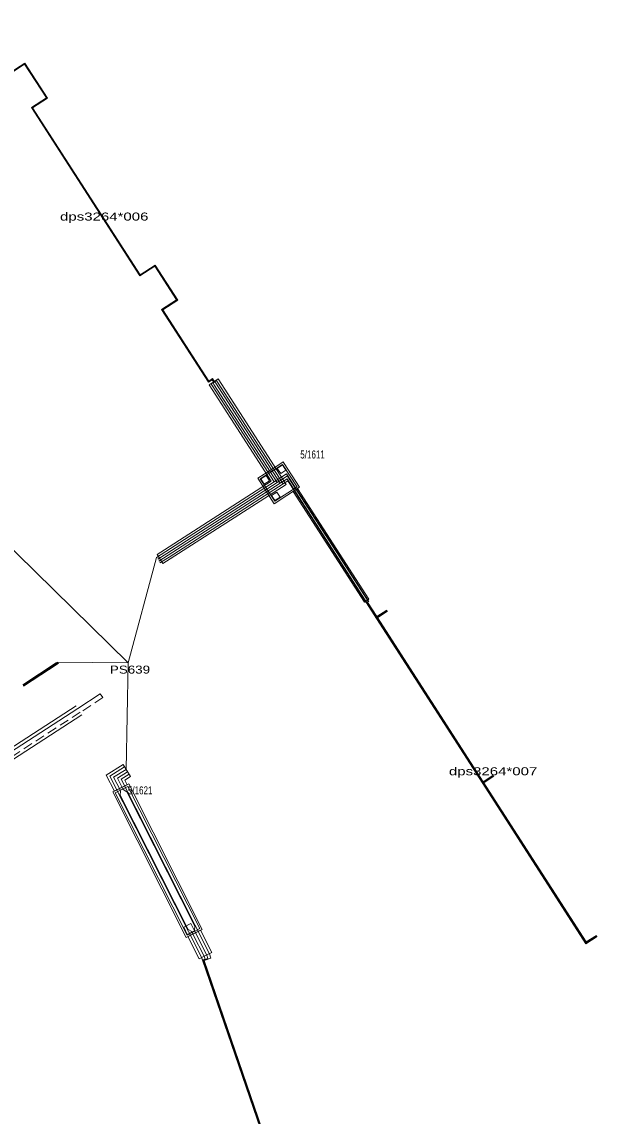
# Model space of a CAD drawing. Extents: x -473467 to -473049, y -1106745 to -1106181.
# Drawn here: x -473135.6 to -473071, y -1106543.7 to -1106420.7 of the extents above; entities that cross this region are included whole.
import ezdxf
from ezdxf.enums import TextEntityAlignment as Align

# ---------------------------------------------------------------- set-up
doc = ezdxf.new("R2010")
doc.units = 0
doc.header["$LTSCALE"] = 0.36
doc.linetypes.add('MEDIUM_DASHED', pattern=[4.5, 3, -1.5])
for name, color, linetype, lineweight in [('1', 7, 'MEDIUM_DASHED', 13), ('11', 7, 'Continuous', 13), ('14', 7, 'Continuous', 13), ('15', 7, 'Continuous', 13), ('17', 7, 'Continuous', 13), ('7', 7, 'Continuous', 13)]:
    doc.layers.add(name, color=color, linetype=linetype, lineweight=lineweight)
for name, color, linetype in [('16', 7, 'Continuous'), ('19', 7, 'Continuous'), ('9', 7, 'Continuous')]:
    doc.layers.add(name, color=color, linetype=linetype)

msp = doc.modelspace()

# ---------------------------------------------------------------- linework, layer by layer
at = {"layer": '1', "linetype": 'Continuous'}
msp.add_lwpolyline([(-473238.151, -1106496.572), (-473233.916, -1106494.611), (-473233.253, -1106494.854), (-473219.66, -1106524.241), (-473218.952, -1106524.731), (-473210.178, -1106525.371), (-473209.213, -1106525.228), (-473205.294, -1106523.722), (-473204.636, -1106524.005), (-473200.526, -1106535.348), (-473199.857, -1106535.779), (-473186.652, -1106534.741), (-473185.734, -1106534.43), (-473129.308, -1106497.84), (-473126.788, -1106496.206)], dxfattribs=at)
at = {"layer": '1'}
msp.add_lwpolyline([(-473126.788, -1106496.206), (-473126.498, -1106496.613), (-473129.036, -1106498.26), (-473185.568, -1106534.919), (-473186.486, -1106535.23), (-473200.197, -1106536.307), (-473200.867, -1106535.877), (-473204.951, -1106524.662), (-473205.589, -1106524.371), (-473209.138, -1106525.735), (-473210.103, -1106525.878), (-473219.282, -1106525.209), (-473219.991, -1106524.719), (-473233.497, -1106495.518), (-473234.16, -1106495.275), (-473237.921, -1106497.017)], dxfattribs=at)
at = {"layer": '11'}
for p, q in [((-473141.383, -1106475.297), (-473123.66, -1106492.696)), ((-473120.467, -1106480.867), (-473123.66, -1106492.696)), ((-473131.524, -1106492.704), (-473135.428, -1106495.272)), ((-473131.579, -1106492.62), (-473123.66, -1106492.696)), ((-473123.886, -1106504.681), (-473123.66, -1106492.696))]:
    msp.add_line(p, q, dxfattribs=at)
for points in [[(-473140.469, -1106420.814), (-473140.587, -1106420.89), (-473136.964, -1106426.509), (-473135.283, -1106425.426), (-473132.845, -1106429.208), (-473134.526, -1106430.291), (-473122.335, -1106449.202), (-473120.654, -1106448.119), (-473118.216, -1106451.901), (-473119.897, -1106452.985), (-473114.632, -1106461.152), (-473114.211, -1106460.881), (-473114.034, -1106461.157)], [(-473140.251, -1106420.71), (-473140.545, -1106420.899), (-473136.955, -1106426.468), (-473135.274, -1106425.384), (-473132.804, -1106429.217), (-473134.485, -1106430.3), (-473122.326, -1106449.161), (-473120.645, -1106448.077), (-473118.174, -1106451.91), (-473119.855, -1106452.994), (-473114.623, -1106461.11), (-473114.202, -1106460.839), (-473114.033, -1106461.102), (-473113.989, -1106461.171)], [(-473140.001, -1106420.655), (-473140.471, -1106420.959), (-473140.413, -1106421.049), (-473136.947, -1106426.426), (-473135.266, -1106425.343), (-473132.762, -1106429.226), (-473134.443, -1106430.309), (-473122.317, -1106449.119), (-473120.636, -1106448.036), (-473118.133, -1106451.919), (-473119.814, -1106453.003), (-473114.614, -1106461.069), (-473114.193, -1106460.798), (-473114.008, -1106461.086), (-473113.963, -1106461.155)], [(-473139.669, -1106420.727), (-473140.14, -1106421.03), (-473140.316, -1106421.144), (-473136.938, -1106426.385), (-473135.257, -1106425.301), (-473132.721, -1106429.235), (-473134.402, -1106430.318), (-473122.308, -1106449.078), (-473120.627, -1106447.994), (-473118.091, -1106451.928), (-473119.772, -1106453.011), (-473114.605, -1106461.027), (-473114.185, -1106460.756), (-473113.957, -1106461.109)], [(-473114.034, -1106461.157), (-473114.335, -1106461.353), (-473114.219, -1106461.534), (-473107.241, -1106472.358)], [(-473113.989, -1106461.171), (-473114.115, -1106461.252), (-473114.017, -1106461.404), (-473106.909, -1106472.43)], [(-473113.963, -1106461.155), (-473113.913, -1106461.123), (-473113.815, -1106461.274), (-473106.577, -1106472.502)], [(-473113.957, -1106461.109), (-473113.73, -1106460.964), (-473113.613, -1106461.144), (-473106.245, -1106472.574)], [(-473107.241, -1106472.358), (-473105.854, -1106471.466), (-473100.257, -1106480.166)], [(-473107.241, -1106472.358), (-473119.436, -1106480.203), (-473120.467, -1106480.867)], [(-473106.909, -1106472.43), (-473119.306, -1106480.405), (-473120.337, -1106481.069)], [(-473106.577, -1106472.502), (-473119.176, -1106480.607), (-473120.208, -1106481.271)], [(-473106.245, -1106472.574), (-473119.046, -1106480.809), (-473120.078, -1106481.473)], [(-473100.296, -1106480.197), (-473105.755, -1106471.712), (-473105.766, -1106471.695), (-473106.909, -1106472.43)], [(-473106.577, -1106472.502), (-473105.804, -1106472.005), (-473100.47, -1106480.297)], [(-473106.245, -1106472.574), (-473105.716, -1106472.234), (-473105.408, -1106472.713), (-473100.512, -1106480.323)], [(-473100.257, -1106480.166), (-473096.732, -1106485.645), (-473096.72, -1106485.664)], [(-473100.512, -1106480.323), (-473096.984, -1106485.808), (-473096.97, -1106485.83)], [(-473100.47, -1106480.297), (-473096.942, -1106485.781), (-473096.928, -1106485.803)], [(-473096.765, -1106485.687), (-473096.774, -1106485.672), (-473100.296, -1106480.197)], [(-473096.97, -1106485.83), (-473096.876, -1106485.976), (-473095.763, -1106487.705), (-473094.502, -1106486.894), (-473095.763, -1106487.705), (-473083.82, -1106506.271), (-473082.558, -1106505.46), (-473083.82, -1106506.271), (-473072.23, -1106524.287), (-473070.968, -1106523.476)], [(-473096.928, -1106485.803), (-473096.834, -1106485.949), (-473096.834, -1106485.949), (-473095.748, -1106487.636), (-473094.539, -1106486.858), (-473095.748, -1106487.636), (-473083.805, -1106506.202), (-473082.594, -1106505.425), (-473083.805, -1106506.202), (-473072.215, -1106524.218), (-473070.995, -1106523.434)], [(-473071.023, -1106523.392), (-473072.2, -1106524.149), (-473083.79, -1106506.133), (-473082.63, -1106505.387), (-473083.79, -1106506.133), (-473095.733, -1106487.567), (-473094.558, -1106486.808), (-473095.733, -1106487.567), (-473096.792, -1106485.922), (-473096.819, -1106485.88), (-473096.693, -1106485.798), (-473096.765, -1106485.687)], [(-473096.72, -1106485.664), (-473096.624, -1106485.813), (-473096.75, -1106485.895), (-473095.718, -1106487.498), (-473094.593, -1106486.77), (-473095.718, -1106487.498), (-473083.775, -1106506.064), (-473082.653, -1106505.343), (-473083.775, -1106506.064), (-473072.185, -1106524.08), (-473071.05, -1106523.35)], [(-473135.483, -1106495.189), (-473131.724, -1106492.716), (-473131.579, -1106492.62)], [(-473135.456, -1106495.231), (-473131.696, -1106492.757), (-473131.551, -1106492.662)], [(-473135.401, -1106495.314), (-473131.641, -1106492.841), (-473131.496, -1106492.745)], [(-473124.056, -1106504.409), (-473124.056, -1106504.409), (-473125.7, -1106505.436), (-473115.407, -1106525.803), (-473115.3, -1106526.116)], [(-473123.886, -1106504.681), (-473123.886, -1106504.681), (-473125.283, -1106505.552), (-473124.554, -1106506.994), (-473124.543, -1106507.016), (-473124.514, -1106507.074), (-473124.556, -1106507.59), (-473116.927, -1106522.686), (-473116.507, -1106522.918), (-473116.332, -1106523.265), (-473115.112, -1106525.678), (-473115.002, -1106525.997)], [(-473123.717, -1106504.952), (-473123.717, -1106504.952), (-473124.865, -1106505.669), (-473124.409, -1106506.572), (-473124.228, -1106506.93), (-473123.788, -1106507.202), (-473116.159, -1106522.298), (-473116.218, -1106522.779), (-473116.051, -1106523.111), (-473114.816, -1106525.553), (-473114.684, -1106525.941)], [(-473123.548, -1106505.224), (-473123.548, -1106505.224), (-473124.448, -1106505.786), (-473114.521, -1106525.429), (-473114.365, -1106525.884)], [(-473115.3, -1106526.116), (-473097.408, -1106578.227), (-473097.077, -1106579.184), (-473096.718, -1106579.06), (-473096.399, -1106578.95)], [(-473115.002, -1106525.997), (-473115.258, -1106526.085), (-473097.413, -1106578.06), (-473097.361, -1106578.211), (-473097.046, -1106579.121), (-473096.74, -1106579.015), (-473096.455, -1106578.916)], [(-473114.684, -1106525.941), (-473115.194, -1106526.116), (-473097.366, -1106578.043), (-473097.314, -1106578.195), (-473097.015, -1106579.057), (-473096.761, -1106578.969), (-473096.525, -1106578.888)], [(-473114.365, -1106525.884), (-473115.131, -1106526.147), (-473097.318, -1106578.027), (-473097.266, -1106578.178), (-473096.985, -1106578.993), (-473096.766, -1106578.918), (-473096.579, -1106578.853)]]:
    msp.add_lwpolyline(points, dxfattribs=at)
at = {"layer": '14'}
for points in [[(-473108.816, -1106472.018), (-473106.295, -1106470.393), (-473104.669, -1106472.914), (-473107.191, -1106474.54), (-473108.816, -1106472.018)], [(-473125.112, -1106507.31), (-473123.684, -1106506.589), (-473115.603, -1106522.577), (-473117.031, -1106523.299), (-473125.112, -1106507.31)]]:
    msp.add_lwpolyline(points, close=True, dxfattribs=at)
at = {"layer": '15'}
for points in [[(-473106.31, -1106470.462), (-473106.898, -1106470.841), (-473106.519, -1106471.429), (-473105.931, -1106471.05)], [(-473108.747, -1106472.033), (-473108.159, -1106471.654), (-473107.78, -1106472.242), (-473108.368, -1106472.621)], [(-473107.176, -1106474.47), (-473106.588, -1106474.091), (-473106.967, -1106473.503), (-473107.555, -1106473.882)], [(-473117.415, -1106522.428), (-473116.612, -1106522.023), (-473116.206, -1106522.826), (-473117.009, -1106523.232), (-473117.415, -1106522.428)]]:
    msp.add_lwpolyline(points, close=True, dxfattribs=at)
at = {"layer": '17'}
for points in [[(-473119.566, -1106480.002), (-473107.573, -1106472.286), (-473114.562, -1106461.445), (-473113.554, -1106460.795), (-473105.913, -1106472.646), (-473118.916, -1106481.011), (-473119.757, -1106481.552), (-473120.407, -1106480.543)], [(-473106.235, -1106470.116), (-473106.403, -1106470.225), (-473107.664, -1106471.037), (-473109.093, -1106471.958), (-473107.251, -1106474.816), (-473104.393, -1106472.974), (-473106.127, -1106470.284)], [(-473105.124, -1106473.445), (-473097.11, -1106485.889), (-473096.606, -1106485.564), (-473096.606, -1106485.564), (-473104.624, -1106473.123)], [(-473124.225, -1106504.138), (-473123.378, -1106505.495), (-473124.028, -1106505.901), (-473123.774, -1106506.41), (-473125.202, -1106507.132), (-473126.113, -1106505.316)], [(-473117.12, -1106523.568), (-473115.335, -1106522.666), (-473123.595, -1106506.32), (-473125.38, -1106507.222)]]:
    msp.add_lwpolyline(points, close=True, dxfattribs=at)
msp.add_lwpolyline([(-473115.678, -1106525.977), (-473114.964, -1106525.616), (-473114.25, -1106525.255), (-473115.513, -1106522.756), (-473116.941, -1106523.477), (-473115.677, -1106525.978)], dxfattribs=at)
at = {"layer": '7'}
for points in [[(-473238.239, -1106496.227), (-473233.292, -1106493.936), (-473219.383, -1106524.008), (-473218.831, -1106524.389), (-473210.191, -1106525.019), (-473209.302, -1106524.888), (-473204.62, -1106523.088), (-473200.237, -1106535.118), (-473199.767, -1106535.421), (-473186.723, -1106534.396), (-473185.887, -1106534.113), (-473129.499, -1106497.546)], [(-473237.735, -1106497.316), (-473233.877, -1106495.529), (-473220.012, -1106525.506), (-473209.552, -1106526.269), (-473205.329, -1106524.647), (-473200.933, -1106536.716), (-473185.872, -1106535.533), (-473128.846, -1106498.553)]]:
    msp.add_lwpolyline(points, dxfattribs=at)

# ---------------------------------------------------------------- texts
at = {"layer": '16', "width": 0.75}
for s, p in [('5/1611', (-473104.316, -1106469.733)), ('5/1621', (-473123.684, -1106507.489))]:
    msp.add_text(s, height=0.9, dxfattribs=at).set_placement(p)
at = {"layer": '19', "width": 1.4}
for s, p in [('dps3264*006', (-473126.341, -1106442.989)), ('dps3264*007', (-473082.653, -1106505.343))]:
    msp.add_text(s, height=0.9, dxfattribs=at).set_placement(p, align=Align.CENTER)
at = {"layer": '9', "width": 1.25}
msp.add_text('PS639', height=0.9, dxfattribs=at).set_placement((-473123.448, -1106493.915), align=Align.CENTER)

doc.saveas('drawing.dxf')
